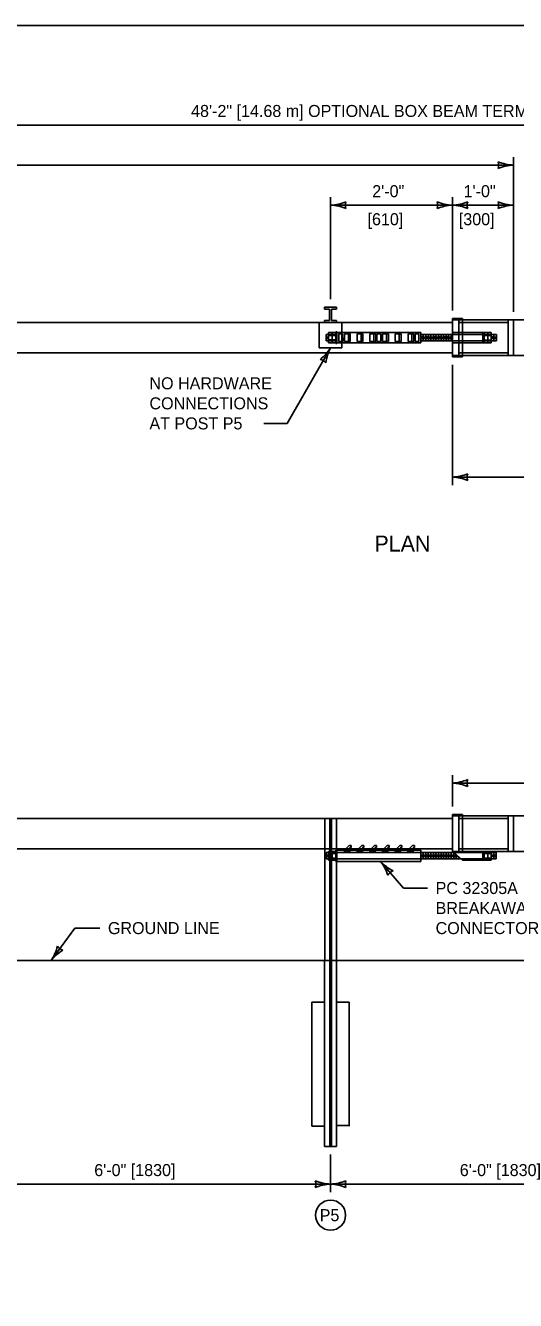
# Model space of a CAD drawing. Extents: x 49991.4 to 50021, y 49987.6 to 50011.4.
# Drawn here: x 50006.18 to 50008.63, y 49992.64 to 49999 of the extents above; entities that cross this region are included whole.
import ezdxf

# ---------------------------------------------------------------- set-up
doc = ezdxf.new("R2010")
doc.units = 0
for name, color, linetype in [('Level 1', 7, 'Continuous'), ('Level 2', 7, 'Continuous'), ('Level 3', 7, 'Continuous'), ('Level 4', 7, 'Continuous')]:
    doc.layers.add(name, color=color, linetype=linetype)

msp = doc.modelspace()

# ---------------------------------------------------------------- linework, layer by layer
at = {"layer": 'Level 1'}
for p, q in [((50007.6748, 49997.5846), (50007.6748, 49997.5938)), ((50007.7338, 49997.5938), (50007.6748, 49997.5938)), ((50007.6997, 49997.5846), (50007.6748, 49997.5846)), ((50007.6997, 49997.527), (50007.6997, 49997.5846)), ((50007.7089, 49997.527), (50007.7089, 49997.5846)), ((50007.7338, 49997.5846), (50007.7089, 49997.5846)), ((50007.7338, 49997.5846), (50007.7338, 49997.5938)), ((50008.3123, 49997.5178), (50001.3379, 49997.5178)), ((50007.6997, 49997.527), (50007.6748, 49997.527)), ((50007.6748, 49997.5178), (50007.6748, 49997.527)), ((50007.7338, 49997.527), (50007.7089, 49997.527)), ((50007.7338, 49997.5178), (50007.7338, 49997.527)), ((50008.3123, 49997.347), (50008.3123, 49997.5369)), ((50008.363, 49997.5369), (50008.3123, 49997.5369)), ((50008.3629, 49997.3469), (50008.363, 49997.5369)), ((50015.4527, 49997.53), (50008.363, 49997.5304)), ((50008.363, 49997.347), (50008.3123, 49997.347)), ((50009.4706, 49997.3533), (50008.363, 49997.3532)), ((50008.3121, 49995.0439), (49999.9212, 49995.0439)), ((50008.3121, 49994.8732), (50008.3121, 49995.0629)), ((50008.3628, 49995.0629), (50008.3121, 49995.0629)), ((50008.3628, 49994.8732), (50008.3628, 49995.0629)), ((50009.4706, 49995.0567), (50008.3628, 49995.0567)), ((50008.3121, 49994.892), (49999.9212, 49994.892)), ((50007.675, 49994.335), (50007.675, 49994.892)), ((50007.7298, 49994.8858), (50008.1538, 49994.8858)), ((50007.7298, 49994.829), (50007.7298, 49994.8858)), ((50007.734, 49994.8858), (50007.734, 49994.892)), ((50007.7361, 49994.829), (50007.7361, 49994.8858)), ((50007.7455, 49994.8858), (50007.7455, 49994.8891)), ((50007.7645, 49994.8891), (50007.7455, 49994.8891)), ((50007.7645, 49994.8858), (50007.7645, 49994.8891)), ((50007.7803, 49994.892), (50007.7741, 49994.8858)), ((50007.7998, 49994.8858), (50007.7998, 49994.892)), ((50007.8437, 49994.892), (50007.8373, 49994.8858)), ((50007.8632, 49994.8858), (50007.8632, 49994.892)), ((50007.907, 49994.892), (50007.9007, 49994.8858)), ((50007.9264, 49994.8858), (50007.9264, 49994.892)), ((50007.9355, 49994.8858), (50007.9355, 49994.8891)), ((50007.9545, 49994.8891), (50007.9355, 49994.8891)), ((50007.9545, 49994.8858), (50007.9545, 49994.8891)), ((50007.9702, 49994.892), (50007.9639, 49994.8858)), ((50007.9898, 49994.8858), (50007.9898, 49994.892)), ((50008.0335, 49994.892), (50008.0271, 49994.8858)), ((50008.0531, 49994.8858), (50008.0531, 49994.892)), ((50008.0969, 49994.892), (50008.0905, 49994.8858)), ((50008.1163, 49994.8858), (50008.1163, 49994.892)), ((50008.1444, 49994.8891), (50008.1254, 49994.8891)), ((50008.1254, 49994.8858), (50008.1254, 49994.8891)), ((50008.1444, 49994.8858), (50008.1444, 49994.8891)), ((50008.1538, 49994.829), (50008.1538, 49994.8858)), ((50007.6817, 49994.8732), (50007.6944, 49994.8732)), ((50007.6817, 49994.8415), (50007.6817, 49994.8732)), ((50007.6944, 49994.8415), (50007.6817, 49994.8415)), ((50007.6883, 49994.8506), (50007.6883, 49994.8641)), ((50007.6944, 49994.8353), (50007.6944, 49994.8794)), ((50007.7298, 49994.8794), (50007.6944, 49994.8794)), ((50007.6944, 49994.869), (50007.7298, 49994.869)), ((50007.7298, 49994.8459), (50007.6944, 49994.8459)), ((50007.7298, 49994.8353), (50007.6944, 49994.8353)), ((50007.7121, 49994.8353), (50007.7121, 49994.8794)), ((50007.7298, 49994.8353), (50007.7298, 49994.8794)), ((50007.7298, 49994.829), (50008.1538, 49994.829)), ((50007.734, 49994.335), (50007.734, 49994.829)), ((50008.1538, 49994.8415), (50008.1538, 49994.8732)), ((50008.1538, 49994.8732), (50008.3193, 49994.8732)), ((50008.3555, 49994.8415), (50008.1538, 49994.8415)), ((50008.1602, 49994.8506), (50008.1602, 49994.8641)), ((50008.1665, 49994.8415), (50008.1665, 49994.8732)), ((50008.173, 49994.8506), (50008.173, 49994.8641)), ((50008.1791, 49994.8415), (50008.1791, 49994.8732)), ((50008.1855, 49994.8506), (50008.1855, 49994.8641)), ((50008.1919, 49994.8415), (50008.1919, 49994.8732)), ((50008.1981, 49994.8506), (50008.1981, 49994.8641)), ((50008.2046, 49994.8415), (50008.2046, 49994.8732)), ((50008.211, 49994.8506), (50008.211, 49994.8641)), ((50008.2172, 49994.8415), (50008.2172, 49994.8732)), ((50008.2235, 49994.8506), (50008.2235, 49994.8641)), ((50008.2298, 49994.8415), (50008.2298, 49994.8732)), ((50008.2363, 49994.8506), (50008.2363, 49994.8641)), ((50008.2425, 49994.8415), (50008.2425, 49994.8732)), ((50008.2489, 49994.8506), (50008.2489, 49994.8641)), ((50008.2553, 49994.8415), (50008.2553, 49994.8732)), ((50008.2616, 49994.8506), (50008.2616, 49994.8641)), ((50008.2678, 49994.8415), (50008.2678, 49994.8732)), ((50008.2741, 49994.8506), (50008.2741, 49994.8641)), ((50008.2805, 49994.8415), (50008.2805, 49994.8732)), ((50008.287, 49994.8506), (50008.287, 49994.8641)), ((50008.2931, 49994.8415), (50008.2931, 49994.8732)), ((50008.2996, 49994.8506), (50008.2996, 49994.8641)), ((50008.306, 49994.8415), (50008.306, 49994.8732)), ((50008.3123, 49994.8506), (50008.3123, 49994.8641)), ((50008.3186, 49994.8415), (50008.3186, 49994.8732)), ((50008.3192, 49994.8732), (50008.3628, 49994.8353)), ((50008.3248, 49994.8506), (50008.3248, 49994.8641)), ((50008.3313, 49994.8415), (50008.3313, 49994.8628)), ((50008.3377, 49994.8506), (50008.3377, 49994.8572)), ((50008.344, 49994.8415), (50008.344, 49994.8517)), ((50009.4706, 49994.8794), (50008.3628, 49994.8794)), ((50008.5057, 49994.8353), (50008.3628, 49994.8353)), ((50008.4639, 49994.8353), (50008.4639, 49994.8794)), ((50008.4703, 49994.8353), (50008.4703, 49994.8794)), ((50008.4703, 49994.869), (50008.5057, 49994.869)), ((50008.5057, 49994.8459), (50008.4703, 49994.8459)), ((50008.488, 49994.8353), (50008.488, 49994.8794)), ((50008.5057, 49994.8353), (50008.5057, 49994.8794)), ((50008.5057, 49994.8732), (50008.5309, 49994.8732)), ((50008.5309, 49994.8415), (50008.5057, 49994.8415)), ((50008.5118, 49994.8506), (50008.5118, 49994.8641)), ((50008.5184, 49994.8415), (50008.5184, 49994.8732)), ((50008.5248, 49994.8506), (50008.5248, 49994.8641)), ((50008.5309, 49994.8415), (50008.5309, 49994.8732)), ((49999.9212, 49994.335), (50016.2933, 49994.335))]:
    msp.add_line(p, q, dxfattribs=at)
msp.add_lwpolyline([(49999.3835, 49998.9992), (50016.7501, 49998.9992), (50016.7501, 49987.7988), (49999.3835, 49987.7988)], close=True, dxfattribs=at)
for points in [[(50001.3379, 49997.3659), (50008.3123, 49997.3659)], [(50008.3628, 49994.8732), (50008.3192, 49994.8732)]]:
    msp.add_lwpolyline(points, dxfattribs=at)
at = {"layer": 'Level 2'}
msp.add_circle((50007.7044, 49993.0644), 0.075, dxfattribs=at)
at = {"layer": 'Level 3'}
for p, q in [((50015.9211, 49998.5028), (50001.3238, 49998.5028)), ((50008.616, 49997.5704), (50008.616, 49998.3428)), ((50008.616, 49998.3028), (50001.3238, 49998.3028)), ((50007.7046, 49997.6338), (50007.7046, 49998.1428)), ((50008.3121, 49997.5769), (50008.3121, 49998.1428)), ((50008.3121, 49998.1028), (50007.7046, 49998.1028)), ((50008.616, 49998.1028), (50008.3121, 49998.1028)), ((50007.4873, 49997.0143), (50007.7043, 49997.3912)), ((50008.3123, 49997.307), (50008.3123, 49996.7066)), ((50007.4873, 49997.0143), (50007.3722, 49997.0143)), ((50015.6047, 49996.7466), (50008.3123, 49996.7466)), ((50008.3121, 49995.1029), (50008.3121, 49995.2602)), ((50009.5276, 49995.2202), (50008.3121, 49995.2202)), ((50008.0673, 49994.6965), (50007.9534, 49994.829)), ((50008.1882, 49994.6965), (50008.0673, 49994.6965)), ((50006.4292, 49994.4965), (50006.3109, 49994.335)), ((50006.554, 49994.4965), (50006.4292, 49994.4965)), ((50007.7044, 49993.3671), (50007.7044, 49993.1794)), ((50007.7048, 49993.2194), (50005.8818, 49993.2194)), ((50009.5278, 49993.2194), (50007.7048, 49993.2194))]:
    msp.add_line(p, q, dxfattribs=at)
for centre, radius, start, end in [((50008.6252, 49998.5249), 0.2223, 247.45601, 267.63952), ((50008.4878, 49998.3028), 0.0548, 342.13882, 17.86118), ((50008.6275, 49998.0701), 0.233, 92.82731, 112.07716), ((50007.6931, 49998.3355), 0.233, 272.82731, 292.07716), ((50007.6954, 49997.8807), 0.2223, 67.45601, 87.63952), ((50007.8328, 49998.1028), 0.0548, 162.13882, 197.86118), ((50008.3213, 49998.3249), 0.2223, 247.45601, 267.63952), ((50008.1839, 49998.1028), 0.0548, 342.13882, 17.86118), ((50008.3236, 49997.8701), 0.233, 92.82731, 112.07716), ((50008.3006, 49998.3355), 0.233, 272.82731, 292.07716), ((50008.3029, 49997.8807), 0.2223, 67.45601, 87.63952), ((50008.4403, 49998.1028), 0.0548, 162.13882, 197.86118), ((50008.6252, 49998.3249), 0.2223, 247.45601, 267.63952), ((50008.4878, 49998.1028), 0.0548, 342.13882, 17.86118), ((50008.6275, 49997.8701), 0.233, 92.82731, 112.07716), ((50007.5164, 49997.51), 0.2223, 307.52484, 327.70835), ((50007.9117, 49997.285), 0.233, 152.89614, 172.14599), ((50007.6403, 49997.2801), 0.0548, 42.20765, 77.93001), ((50008.3008, 49996.9793), 0.233, 272.82731, 292.07716), ((50008.3031, 49996.5245), 0.2223, 67.45601, 87.63952), ((50008.4405, 49996.7466), 0.0548, 162.13882, 197.86118), ((50008.3006, 49995.4529), 0.233, 272.82731, 292.07716), ((50008.3029, 49994.9981), 0.2223, 67.45601, 87.63952), ((50008.4403, 49995.2202), 0.0548, 162.13882, 197.86118), ((50007.779, 49994.6911), 0.2223, 18.13911, 38.32262), ((50008.1224, 49994.9894), 0.233, 223.51041, 242.76026), ((50008.037, 49994.7318), 0.0548, 112.82192, 148.54428), ((50006.1164, 49994.4633), 0.233, 326.59909, 345.84894), ((50006.4847, 49994.1963), 0.2223, 121.22779, 141.4113), ((50006.3867, 49994.4384), 0.0548, 215.9106, 251.63296), ((50007.7136, 49993.4415), 0.2223, 247.45601, 267.63952), ((50007.5762, 49993.2194), 0.0548, 342.13882, 17.86118), ((50007.6929, 49993.4521), 0.233, 272.82731, 292.07716), ((50007.8326, 49993.2194), 0.0548, 162.13882, 197.86118), ((50007.7159, 49992.9867), 0.233, 92.82731, 112.07716), ((50007.6952, 49992.9973), 0.2223, 67.45601, 87.63952)]:
    msp.add_arc(centre, radius, start, end, dxfattribs=at)
at = {"layer": 'Level 4'}
for p, q in [((50007.6473, 49997.3912), (50007.6473, 49997.5178)), ((50007.7613, 49997.3912), (50007.7613, 49997.5178)), ((50008.363, 49997.5304), (50008.3123, 49997.5304)), ((50008.3442, 49997.3533), (50008.3442, 49997.5304)), ((50008.5908, 49997.5178), (50008.3442, 49997.5177)), ((50008.5908, 49997.3533), (50008.5908, 49997.5304)), ((50008.6162, 49997.3532), (50008.6161, 49997.5304)), ((50007.6819, 49997.426), (50007.6819, 49997.4577)), ((50007.6819, 49997.4576), (50007.7363, 49997.4575)), ((50007.6885, 49997.435), (50007.6885, 49997.4485)), ((50007.6946, 49997.4671), (50007.73, 49997.4671)), ((50007.6946, 49997.4165), (50007.6946, 49997.4671)), ((50007.6946, 49997.4534), (50007.73, 49997.4534)), ((50007.73, 49997.4303), (50007.6946, 49997.4303)), ((50007.7123, 49997.4164), (50007.7123, 49997.467)), ((50007.7363, 49997.4703), (50007.73, 49997.4704)), ((50007.73, 49997.4134), (50007.73, 49997.4704)), ((50007.7363, 49997.4133), (50007.7363, 49997.4703)), ((50008.154, 49997.4671), (50007.7363, 49997.4671)), ((50007.7646, 49997.4609), (50007.7457, 49997.4609)), ((50007.7458, 49997.4228), (50007.7457, 49997.4609)), ((50007.7647, 49997.4229), (50007.7646, 49997.4609)), ((50007.7743, 49997.4229), (50007.7742, 49997.4609)), ((50007.8027, 49997.4609), (50007.7742, 49997.4609)), ((50007.7932, 49997.4229), (50007.7932, 49997.4609)), ((50007.8027, 49997.4229), (50007.8027, 49997.4609)), ((50007.8375, 49997.4229), (50007.8375, 49997.4609)), ((50007.866, 49997.4609), (50007.8375, 49997.4609)), ((50007.8566, 49997.4229), (50007.8566, 49997.4609)), ((50007.866, 49997.4229), (50007.866, 49997.4609)), ((50007.9009, 49997.4229), (50007.9009, 49997.4609)), ((50007.9294, 49997.4609), (50007.9009, 49997.4609)), ((50007.9198, 49997.4229), (50007.9198, 49997.4609)), ((50007.9294, 49997.4229), (50007.9294, 49997.4609)), ((50007.9357, 49997.4229), (50007.9357, 49997.4609)), ((50007.9547, 49997.4609), (50007.9357, 49997.4609)), ((50007.9547, 49997.4229), (50007.9547, 49997.4609)), ((50007.9641, 49997.4229), (50007.9641, 49997.4609)), ((50007.9926, 49997.4608), (50007.9641, 49997.4609)), ((50007.9832, 49997.4229), (50007.9832, 49997.4609)), ((50007.9926, 49997.4229), (50007.9926, 49997.4608)), ((50008.0273, 49997.4229), (50008.0273, 49997.4609)), ((50008.0559, 49997.4608), (50008.0273, 49997.4609)), ((50008.0463, 49997.4229), (50008.0463, 49997.4608)), ((50008.0559, 49997.4228), (50008.0559, 49997.4608)), ((50008.0907, 49997.4229), (50008.0907, 49997.4609)), ((50008.1192, 49997.4608), (50008.0907, 49997.4609)), ((50008.1095, 49997.4228), (50008.1096, 49997.4608)), ((50008.1191, 49997.4228), (50008.1192, 49997.4608)), ((50008.1255, 49997.4229), (50008.1256, 49997.4609)), ((50008.1446, 49997.4609), (50008.1256, 49997.4609)), ((50008.1445, 49997.4229), (50008.1446, 49997.4609)), ((50008.154, 49997.4166), (50008.154, 49997.4671)), ((50008.154, 49997.4576), (50008.5311, 49997.4576)), ((50008.1604, 49997.4351), (50008.1604, 49997.4486)), ((50008.1666, 49997.4261), (50008.1666, 49997.4577)), ((50008.1731, 49997.435), (50008.1731, 49997.4485)), ((50008.1793, 49997.4261), (50008.1793, 49997.4577)), ((50008.1857, 49997.4351), (50008.1857, 49997.4486)), ((50008.192, 49997.426), (50008.192, 49997.4576)), ((50008.1982, 49997.4351), (50008.1982, 49997.4485)), ((50008.2048, 49997.4261), (50008.2048, 49997.4577)), ((50008.2112, 49997.435), (50008.2112, 49997.4485)), ((50008.2174, 49997.426), (50008.2174, 49997.4576)), ((50008.2237, 49997.4351), (50008.2237, 49997.4486)), ((50008.23, 49997.4261), (50008.23, 49997.4577)), ((50008.2365, 49997.435), (50008.2365, 49997.4485)), ((50008.2427, 49997.4261), (50008.2427, 49997.4577)), ((50008.2491, 49997.4351), (50008.2491, 49997.4486)), ((50008.2554, 49997.426), (50008.2554, 49997.4576)), ((50008.2618, 49997.4351), (50008.2618, 49997.4485)), ((50008.268, 49997.4261), (50008.268, 49997.4577)), ((50008.2743, 49997.4351), (50008.2743, 49997.4486)), ((50008.2806, 49997.426), (50008.2807, 49997.4576)), ((50008.2872, 49997.4351), (50008.2872, 49997.4486)), ((50008.2932, 49997.4261), (50008.2933, 49997.4577)), ((50008.2998, 49997.435), (50008.2998, 49997.4485)), ((50008.3061, 49997.4261), (50008.3062, 49997.4577)), ((50008.3123, 49997.4672), (50008.5059, 49997.4671)), ((50008.4641, 49997.4165), (50008.4641, 49997.4671)), ((50008.4705, 49997.4165), (50008.4705, 49997.4671)), ((50008.4705, 49997.4534), (50008.5059, 49997.4533)), ((50008.5059, 49997.4302), (50008.4705, 49997.4303)), ((50008.4882, 49997.4165), (50008.4882, 49997.4671)), ((50008.5059, 49997.4165), (50008.5059, 49997.4671)), ((50008.512, 49997.4351), (50008.512, 49997.4486)), ((50008.5186, 49997.4261), (50008.5186, 49997.4576)), ((50008.525, 49997.435), (50008.525, 49997.4485)), ((50008.5311, 49997.4261), (50008.5311, 49997.4576)), ((50007.7613, 49997.3912), (50007.6473, 49997.3912)), ((50007.7363, 49997.4259), (50007.6819, 49997.4259)), ((50007.73, 49997.4165), (50007.6946, 49997.4165)), ((50007.7363, 49997.4133), (50007.73, 49997.4134)), ((50008.154, 49997.4166), (50007.7363, 49997.4165)), ((50007.7647, 49997.4229), (50007.7458, 49997.4228)), ((50007.8027, 49997.4229), (50007.7743, 49997.4229)), ((50007.866, 49997.4229), (50007.8375, 49997.4229)), ((50007.9294, 49997.4229), (50007.9009, 49997.4229)), ((50007.9547, 49997.4229), (50007.9357, 49997.4229)), ((50007.9926, 49997.4229), (50007.9641, 49997.4229)), ((50008.0559, 49997.4228), (50008.0273, 49997.4229)), ((50008.1191, 49997.4228), (50008.0907, 49997.4229)), ((50008.1445, 49997.4229), (50008.1255, 49997.4229)), ((50008.5311, 49997.4261), (50008.154, 49997.4261)), ((50008.5059, 49997.4165), (50008.3123, 49997.4166)), ((50008.5908, 49997.366), (50008.3442, 49997.3659)), ((50008.363, 49997.3532), (50008.3123, 49997.3533)), ((50007.675, 49994.892), (50007.675, 49995.0439)), ((50007.6999, 49993.4071), (50007.6999, 49995.0439)), ((50007.709, 49993.4071), (50007.709, 49995.0439)), ((50007.734, 49994.892), (50007.734, 49995.0439)), ((50008.3121, 49995.0567), (50008.3628, 49995.0567)), ((50008.3441, 49994.8794), (50008.3441, 49995.0567)), ((50008.5906, 49995.0439), (50008.3441, 49995.0439)), ((50008.5906, 49994.8794), (50008.5906, 49995.0567)), ((50008.616, 49994.8794), (50008.616, 49995.0567)), ((50007.7741, 49994.8793), (50007.7741, 49994.8858)), ((50007.7966, 49994.9084), (50007.7803, 49994.892)), ((50007.8063, 49994.9084), (50007.7966, 49994.9084)), ((50007.7998, 49994.892), (50007.7998, 49994.8954)), ((50007.7998, 49994.8793), (50007.7998, 49994.8858)), ((50007.8063, 49994.8987), (50007.803, 49994.8987)), ((50007.8063, 49994.8987), (50007.8063, 49994.9084)), ((50007.8373, 49994.8793), (50007.8373, 49994.8858)), ((50007.8599, 49994.9084), (50007.8437, 49994.892)), ((50007.8696, 49994.9084), (50007.8599, 49994.9084)), ((50007.8632, 49994.892), (50007.8632, 49994.8954)), ((50007.8632, 49994.8793), (50007.8632, 49994.8858)), ((50007.8696, 49994.8987), (50007.8663, 49994.8987)), ((50007.8696, 49994.8987), (50007.8696, 49994.9084)), ((50007.9007, 49994.8793), (50007.9007, 49994.8858)), ((50007.9231, 49994.9084), (50007.907, 49994.892)), ((50007.9329, 49994.9084), (50007.9231, 49994.9084)), ((50007.9264, 49994.892), (50007.9264, 49994.8954)), ((50007.9264, 49994.8793), (50007.9264, 49994.8858)), ((50007.9329, 49994.8987), (50007.9297, 49994.8987)), ((50007.9329, 49994.8987), (50007.9329, 49994.9084)), ((50007.9639, 49994.8793), (50007.9639, 49994.8858)), ((50007.9866, 49994.9084), (50007.9702, 49994.892)), ((50007.9962, 49994.9084), (50007.9866, 49994.9084)), ((50007.9898, 49994.892), (50007.9898, 49994.8954)), ((50007.9898, 49994.8793), (50007.9898, 49994.8858)), ((50007.9962, 49994.8987), (50007.9929, 49994.8987)), ((50007.9962, 49994.8987), (50007.9962, 49994.9084)), ((50008.0271, 49994.8793), (50008.0271, 49994.8858)), ((50008.0497, 49994.9084), (50008.0335, 49994.892)), ((50008.0594, 49994.9084), (50008.0497, 49994.9084)), ((50008.0531, 49994.892), (50008.0531, 49994.8954)), ((50008.0531, 49994.8793), (50008.0531, 49994.8858)), ((50008.0594, 49994.8987), (50008.0562, 49994.8987)), ((50008.0594, 49994.8987), (50008.0594, 49994.9084)), ((50008.0905, 49994.8793), (50008.0905, 49994.8858)), ((50008.1131, 49994.9084), (50008.0969, 49994.892)), ((50008.1227, 49994.9084), (50008.1131, 49994.9084)), ((50008.1163, 49994.892), (50008.1163, 49994.8954)), ((50008.1163, 49994.8793), (50008.1163, 49994.8858)), ((50008.1227, 49994.8987), (50008.1196, 49994.8987)), ((50008.1227, 49994.8987), (50008.1227, 49994.9084)), ((50008.5906, 49994.892), (50008.3441, 49994.892)), ((50008.1538, 49994.8732), (50007.6944, 49994.8732)), ((50008.1538, 49994.8415), (50007.6944, 49994.8415)), ((50007.7741, 49994.8793), (50007.7998, 49994.8793)), ((50007.8373, 49994.8793), (50007.8632, 49994.8793)), ((50007.9007, 49994.8793), (50007.9264, 49994.8793)), ((50007.9639, 49994.8793), (50007.9898, 49994.8793)), ((50008.0271, 49994.8793), (50008.0531, 49994.8793)), ((50008.0905, 49994.8793), (50008.1163, 49994.8793)), ((50008.3121, 49994.8794), (50008.3628, 49994.8794)), ((50008.5057, 49994.8415), (50008.3555, 49994.8415)), ((50008.3628, 49994.8732), (50008.5057, 49994.8732)), ((50007.6749, 49994.335), (50007.6749, 49993.4071)), ((50007.7339, 49994.335), (50007.7339, 49993.4071)), ((50007.6115, 49994.127), (50007.6749, 49994.127)), ((50007.6115, 49994.127), (50007.6115, 49993.5085)), ((50007.7339, 49994.127), (50007.7972, 49994.127)), ((50007.7972, 49994.127), (50007.7972, 49993.5085)), ((50007.6115, 49993.5085), (50007.6749, 49993.5085)), ((50007.7339, 49993.5119), (50007.7972, 49993.5119)), ((50007.6749, 49993.4071), (50007.7339, 49993.4071))]:
    msp.add_line(p, q, dxfattribs=at)
for centre in [(50007.803, 49994.8954), (50007.8664, 49994.8954), (50007.9296, 49994.8954), (50007.993, 49994.8954), (50008.0562, 49994.8954), (50008.1196, 49994.8954)]:
    msp.add_arc(centre, 0.00322, 90, 180, dxfattribs=at)

# ---------------------------------------------------------------- texts
at = {"layer": 'Level 2'}
for s, height, p in [('48\'-2" [14.68 m] OPTIONAL BOX BEAM TERMINAL SECTION PAY LIMITS', 0.06, (50007.0088, 49998.5428)), ('2\'-0"', 0.06, (50007.9122, 49998.1428)), ('1\'-0"', 0.06, (50008.3679, 49998.1428)), ('[610]', 0.06, (50007.8887, 49998.0028)), ('[300]', 0.06, (50008.344, 49998.0028)), ('NO HARDWARE', 0.06, (50006.801, 49997.1843)), ('CONNECTIONS', 0.06, (50006.801, 49997.0843)), ('AT POST P5', 0.06, (50006.801, 49996.9843)), ('PLAN', 0.08, (50007.923, 49996.3747)), ('PC 32305A', 0.06, (50008.2282, 49994.6665)), ('BREAKAWAY TENSILE', 0.06, (50008.2282, 49994.5665)), ('GROUND LINE', 0.06, (50006.594, 49994.4665)), ('CONNECTOR', 0.06, (50008.2282, 49994.4665)), ('6\'-0" [1830]', 0.06, (50006.5258, 49993.2594)), ('6\'-0" [1830]', 0.06, (50008.3488, 49993.2594)), ('P5', 0.06, (50007.6501, 49993.0344))]:
    msp.add_text(s, height=height, dxfattribs=at).set_placement(p)

doc.saveas('drawing.dxf')
